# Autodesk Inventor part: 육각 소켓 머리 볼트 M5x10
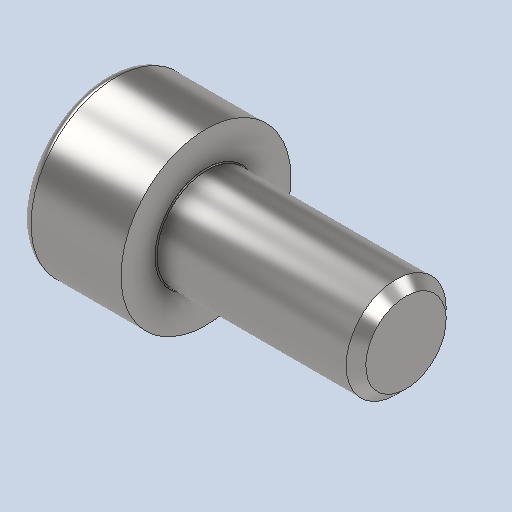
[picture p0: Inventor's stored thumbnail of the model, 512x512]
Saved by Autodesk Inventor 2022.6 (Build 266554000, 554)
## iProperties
Created: 2024-09
Part Number: 육각 소켓 머리 볼트 M5x10
Material: 강철, 연강
Description: 6각머리 태핑 나사
Document SubType Name: Modeling
Designer: Class 001
Density: 7.85 g/cm^3
Appearance: 기본값
Author: jhkim
Sending System: Autodesk Inventor 2025
Preprocessor: ST-DEVELOPER v20
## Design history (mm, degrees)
feature "Solid1"
node "솔리드1"
